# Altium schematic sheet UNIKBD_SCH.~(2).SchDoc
size A4
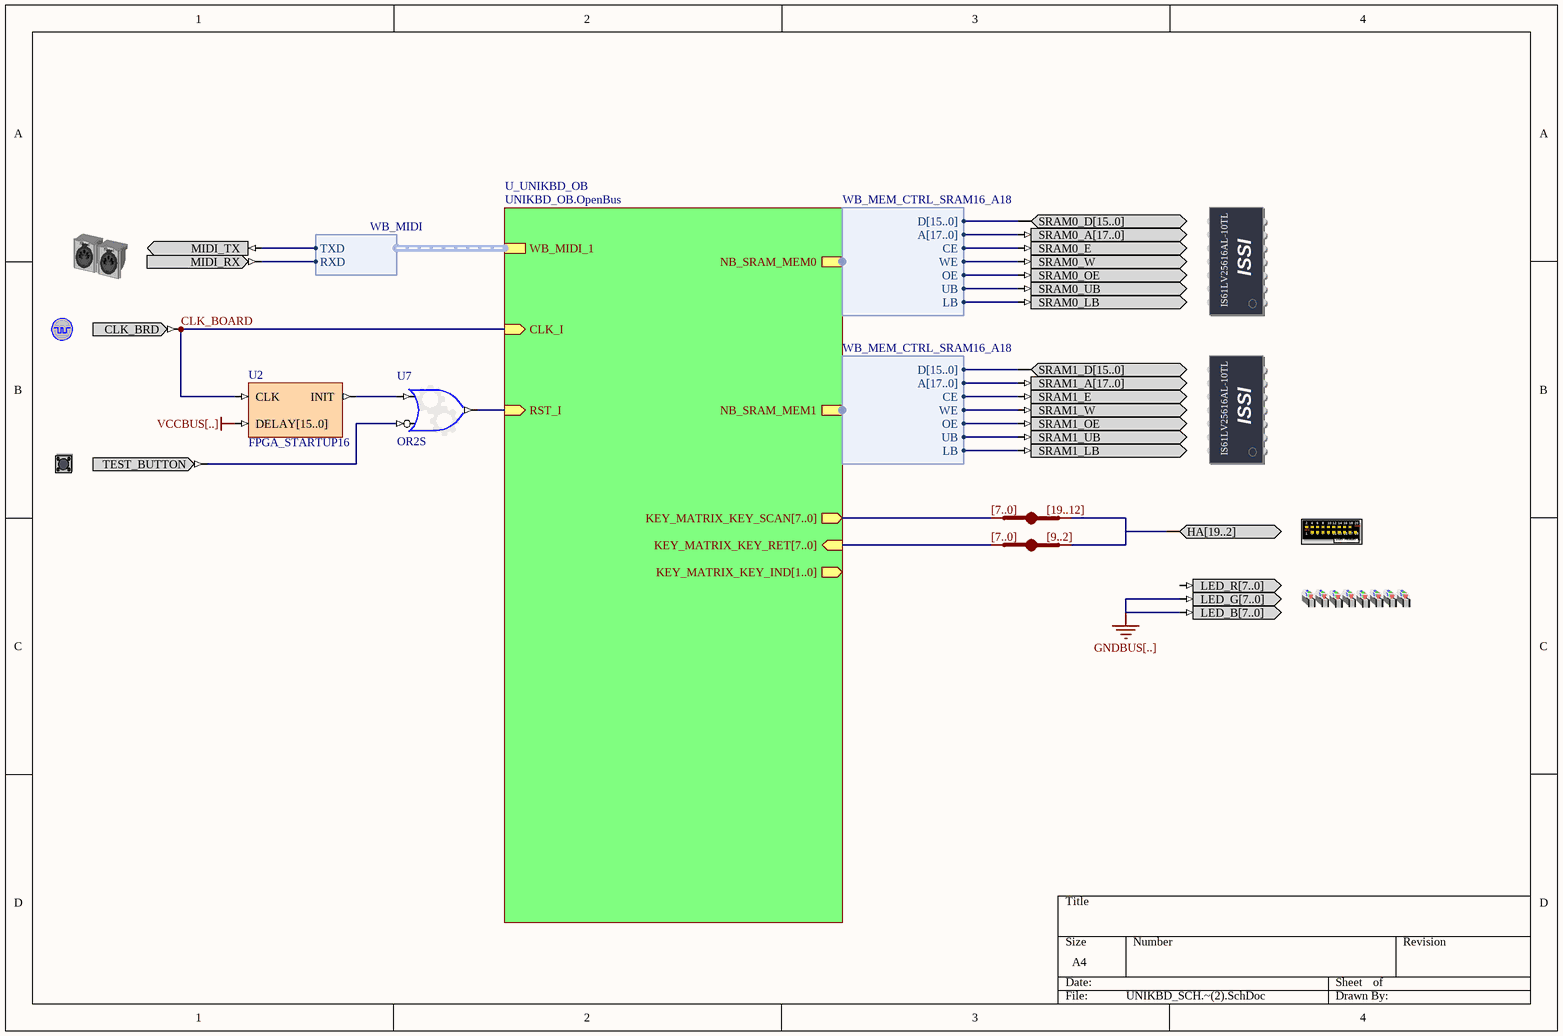
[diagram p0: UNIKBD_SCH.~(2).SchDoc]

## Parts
(Parts that share a designator on the sheet are numbered #1, #2 ... from top to bottom, then left to right.)
?#1  SRAM0  (value not drawn)
?#2  MIDI  (value not drawn)
?#3  CLOCK_BOARD  (value not drawn)
?#4  SRAM1  (value not drawn)
?#5  TEST_BUTTON  (value not drawn)
?#6  USER_HEADER_A  (value not drawn)
?#7  LEDS_RGB  (value not drawn)
JB_AUTO?#1  IndexA: [7..0]  IndexB: [19..12]  (hidden comment: JB)
JB_AUTO?#2  IndexA: [7..0]  IndexB: [9..2]  (hidden comment: JB)
U2  FPGA_STARTUP16
U7  OR2S

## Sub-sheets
U_UNIKBD_OB = UNIKBD_OB.OpenBus: KEY_MATRIX_KEY_SCAN[7..0] (out), KEY_MATRIX_KEY_RET[7..0] (in), KEY_MATRIX_KEY_IND[1..0] (out), WB_MIDI_1 (harness WB_MIDI), NB_SRAM_MEM0 (harness WB_MEM_CTRL_SRAM16_A18), NB_SRAM_MEM1 (harness WB_MEM_CTRL_SRAM16_A18), RST_I (in), CLK_I (in)

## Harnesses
WB_MEM_CTRL_SRAM16_A18: D[15..0], A[17..0], CE, WE, OE, UB, LB
WB_MIDI: RXD, TXD

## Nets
VCCBUS[..]: U2.DELAY[15..0]
CLK_BOARD: ?#3.CLK_BRD U2.CLK ; sheet U_UNIKBD_OB/CLK_I
Net?#1_SRAM0_E: ?#1.SRAM0_E ; sheet U_UNIKBD_OB/NB_SRAM_MEM0.CE
Net?#1_SRAM0_LB: ?#1.SRAM0_LB ; sheet U_UNIKBD_OB/NB_SRAM_MEM0.LB
Net?#1_SRAM0_OE: ?#1.SRAM0_OE ; sheet U_UNIKBD_OB/NB_SRAM_MEM0.OE
Net?#1_SRAM0_UB: ?#1.SRAM0_UB ; sheet U_UNIKBD_OB/NB_SRAM_MEM0.UB
Net?#1_SRAM0_W: ?#1.SRAM0_W ; sheet U_UNIKBD_OB/NB_SRAM_MEM0.WE
Net?#2_MIDI_RX: ?#2.MIDI_RX ; sheet U_UNIKBD_OB/WB_MIDI_1.RXD
Net?#2_MIDI_TX: ?#2.MIDI_TX ; sheet U_UNIKBD_OB/WB_MIDI_1.TXD
Net?#4_SRAM1_E: ?#4.SRAM1_E ; sheet U_UNIKBD_OB/NB_SRAM_MEM1.CE
Net?#4_SRAM1_LB: ?#4.SRAM1_LB ; sheet U_UNIKBD_OB/NB_SRAM_MEM1.LB
Net?#4_SRAM1_OE: ?#4.SRAM1_OE ; sheet U_UNIKBD_OB/NB_SRAM_MEM1.OE
Net?#4_SRAM1_UB: ?#4.SRAM1_UB ; sheet U_UNIKBD_OB/NB_SRAM_MEM1.UB
Net?#4_SRAM1_W: ?#4.SRAM1_W ; sheet U_UNIKBD_OB/NB_SRAM_MEM1.WE
Net?#5_TEST_BUTTON: ?#5.TEST_BUTTON U7.I1
NetU2_INIT: U2.INIT U7.I0
NetU7_O: U7.O ; sheet U_UNIKBD_OB/RST_I

Not connected (* = marked no-connect by the designer): ?#1 SRAM0_A[17..0] SRAM0_D[15..0]; ?#4 SRAM1_A[17..0] SRAM1_D[15..0]; ?#6 HA[19..2]; ?#7 LED_B[7..0] LED_G[7..0] LED_R[7..0]; JB_AUTO?#1 A[0..0] B[0..0]; JB_AUTO?#2 A[0..0] B[0..0]

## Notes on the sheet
- Labels drawn without touching a wire or pin: GNDBUS[..]

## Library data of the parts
?#1 = SRAM0: Free Static RAM - Daughterboard; PortComponent: True
?#2 = MIDI: MIDI Connector; PortComponent: True
?#3 = CLOCK_BOARD: Global System Clock Supply; PortComponent: True
?#4 = SRAM1: Free Static RAM - Daughterboard; PortComponent: True
?#5 = TEST_BUTTON: Test / Reset Button; PortComponent: True
?#6 = USER_HEADER_A: User Header A; PortComponent: True
?#7 = LEDS_RGB: LEDS RGB; PortComponent: True
JB_AUTO?#1 JB_AUTO?#2 = JB: System BUS Joiner
U2 = FPGA_STARTUP16: FPGA Startup With 16 Bit Delay
U7 = GATE: Configurable Generic Gate; ConfiguratorName: GENERIC_GATE; ConfigurationParameters: {}Version[1.0]{}GateKind[OR]{}BusInput[False]{}GateInputType[Bit]{}GateOutputOption[Normal]{}BusWidth[8]{}RegisterOutputs[False]{}NegativeClockEdge[False]{}InputCount[2]{}InputInvert0[False]{}InputInvert1[True]{}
